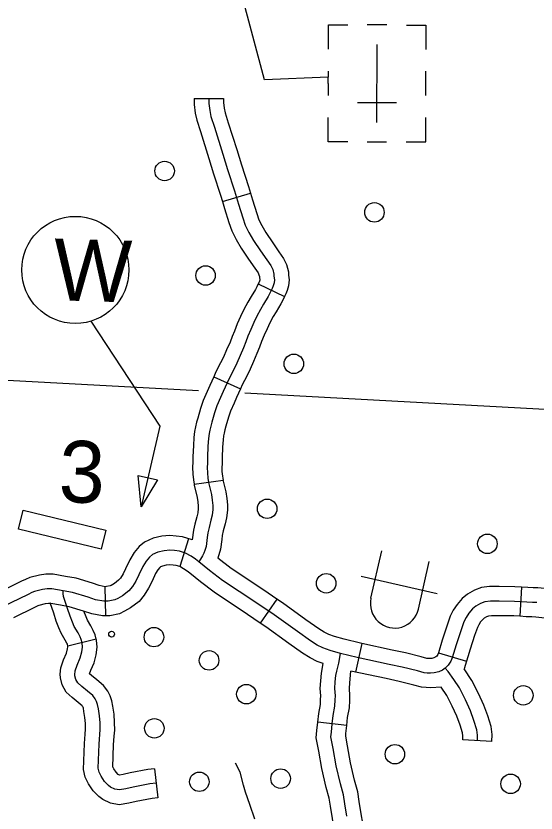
# Model space of a CAD drawing. Extents: x 653372 to 905732, y 627442 to 787275.
# Drawn here: x 716674 to 719343, y 760061 to 764152 of the extents above; entities that cross this region are included whole.
import ezdxf

# ---------------------------------------------------------------- set-up
doc = ezdxf.new("R2010")
doc.units = 0
for name, color, linetype in [('32', 7, 'Continuous'), ('35', 7, 'Continuous'), ('45', 7, 'Continuous'), ('5', 7, 'Continuous'), ('56', 7, 'Continuous'), ('57', 7, 'Continuous')]:
    doc.layers.add(name, color=color, linetype=linetype)

msp = doc.modelspace()

# ---------------------------------------------------------------- linework, layer by layer
at = {"layer": '32'}
for p, q in [((717588.6, 763729.1), (717738.6, 763728.2)), ((717733.7, 763200.2), (717877.3, 763243.3)), ((717917.3, 762776.6), (718053, 762712.7)), ((717689.2, 762299.6), (717826.2, 762238.7)), ((717588.3, 761748.6), (717736.9, 761768.8)), ((717559.5, 761468.8), (717514.7, 761325.7)), ((717130.1, 761222.7), (717133.9, 761072.8)), ((719269.2, 761220.4), (719260.3, 761070.7)), ((718012.9, 761159.2), (717928.2, 761035.4)), ((718449.2, 760931.1), (718417.3, 760784.5)), ((718842.3, 760883.6), (718986, 760840.7)), ((718372.1, 760509.9), (718223.1, 760527.5)), ((719116.7, 760428.7), (718966.9, 760436.1))]:
    msp.add_line(p, q, dxfattribs=at)
for points in [[(717588.6, 763729.1), (717588.4, 763697.9), (717594.6, 763654), (717601.8, 763617.5), (717620.8, 763558.8), (717663.8, 763421.2), (717688.7, 763342), (717724, 763232.5), (717733.7, 763200.2)], [(717663.6, 763728.6), (717663.4, 763703), (717668.6, 763666.6), (717674.6, 763636.4), (717692.3, 763581.5), (717735.3, 763443.6), (717760.1, 763364.8), (717795.6, 763254.8), (717816, 763186.6), (717838.9, 763115.2), (717851.2, 763077.6), (717869.4, 763040.2), (717893.9, 763000.4), (717929.7, 762946.3), (717962.1, 762899.7), (717981.8, 762870.7), (717991.6, 762850.2), (717997.8, 762827.4), (717998.4, 762816.1), (718000.3, 762797.2), (717998.9, 762781.9), (717994.3, 762767.1), (717989.6, 762754.1), (717977.8, 762729), (717968.9, 762711.6), (717945, 762673.1), (717928.8, 762645.8), (717910.9, 762611.9), (717894.6, 762578.7), (717878.9, 762542.9), (717865, 762507.9), (717854.5, 762479.1), (717842, 762448.2), (717824.2, 762408.7), (717808.1, 762370.2), (717791.5, 762337.4), (717767.9, 762292.1), (717737.8, 762224.3), (717724.7, 762194.6), (717704.9, 762150.8), (717692.9, 762115.5), (717679.9, 762067.8), (717673.7, 762046.9), (717668.7, 762026.7), (717665, 762008.4), (717662.4, 761982.5), (717659.6, 761943.2), (717657.7, 761887.6), (717656.8, 761857.2), (717655.1, 761834.8), (717656.5, 761807.2), (717659.7, 761779.9), (717662.8, 761757.4), (717677.8, 761695.5), (717682, 761666.6), (717684.6, 761639.4), (717684.3, 761619.4), (717681.2, 761589.1), (717674.8, 761563.4), (717665.2, 761526.2), (717659.4, 761499.2), (717655.9, 761474.5), (717650.5, 761429.7), (717644.2, 761408.3), (717638.8, 761395.3), (717632.2, 761381.8), (717621.3, 761364), (717612.8, 761351.1)], [(717738.6, 763728.2), (717738.5, 763708.1), (717742.6, 763679.1), (717747.3, 763655.3), (717763.8, 763604.2), (717806.9, 763466.1), (717831.6, 763387.5), (717867.2, 763277.1), (717877.3, 763243.3)], [(717877.3, 763243.3), (717887.7, 763208.8), (717910.2, 763138.2), (717920.9, 763105.8), (717935.3, 763076.3), (717957.1, 763040.7), (717991.8, 762988.4), (718023.9, 762942.2), (718047.1, 762908.1), (718062.2, 762876.4), (718072.2, 762839.6), (718073.2, 762821.8), (718075.6, 762797.4), (718072.8, 762767.5), (718065.5, 762743.2), (718058.9, 762725.1), (718053, 762712.8)], [(717733.7, 763200.2), (717744.4, 763164.4), (717767.5, 763092.1), (717781.5, 763049.3), (717803.6, 763004), (717830.6, 762960), (717867.7, 762904.2), (717900.3, 762857.2), (717916.6, 762833.2), (717921, 762824), (717923.4, 762815.3), (717923.7, 762810.3), (717924.9, 762797), (717924.9, 762796.4), (717923.2, 762790.9), (717920.3, 762783), (717917.3, 762776.6)], [(717917.3, 762776.6), (717910.4, 762762), (717903.5, 762748.4), (717880.8, 762712), (717863.4, 762682.4), (717844.1, 762646), (717826.6, 762610.3), (717809.7, 762571.8), (717794.9, 762534.6), (717784.5, 762506.1), (717773, 762477.7), (717755.4, 762438.6), (717739.9, 762401.6), (717724.7, 762371.6), (717700.3, 762324.7), (717689.2, 762299.6)], [(718053, 762712.8), (718045.2, 762696.1), (718034.3, 762674.7), (718009.1, 762634.2), (717994.3, 762609.2), (717977.8, 762577.9), (717962.7, 762547), (717948.1, 762513.9), (717935.1, 762481.1), (717924.5, 762452.1), (717911, 762418.8), (717893, 762378.9), (717876.2, 762338.7), (717858.2, 762303.1), (717835.5, 762259.6), (717826.2, 762238.7)], [(717689.2, 762299.6), (717669.2, 762254.6), (717656.2, 762225.1), (717635.1, 762178.4), (717621.2, 762137.5), (717607.8, 762088.4), (717601.3, 762066.6), (717595.5, 762043.1), (717590.8, 762019.6), (717587.7, 761988.9), (717584.7, 761947.2), (717582.7, 761890.1), (717581.8, 761861.1), (717580, 761835.6), (717581.7, 761801), (717585.3, 761770.5), (717588.3, 761748.6)], [(717826.2, 762238.7), (717806.3, 762193.9), (717793.2, 762164.1), (717774.8, 762123.2), (717764.7, 762093.6), (717752.1, 762047.2), (717746.1, 762027.1), (717741.9, 762010.3), (717739.3, 761997.2), (717737.1, 761976.1), (717734.6, 761939.3), (717732.6, 761885.2), (717731.7, 761853.4), (717730.3, 761833.9), (717731.3, 761813.5), (717734.1, 761789.4), (717736.9, 761768.8)], [(717736.6, 761771.3), (717751.6, 761709.7), (717756.5, 761675.5), (717759.6, 761642.4), (717759.2, 761615), (717755.3, 761576.2), (717747.5, 761545), (717738.3, 761509), (717733.3, 761485.9), (717730.2, 761464.7), (717724.2, 761414.5), (717710.7, 761368.4)], [(717588.3, 761748.7), (717589, 761743.4), (717604.1, 761681.3), (717607.5, 761657.7), (717609.5, 761636.3), (717609.3, 761623.7), (717607.1, 761602.1), (717602.1, 761581.8), (717592.2, 761543.4), (717585.6, 761512.4), (717578.4, 761462.9)], [(717578.4, 761462.9), (717529.3, 761478.3), (717496.4, 761482.6), (717463.7, 761485.3), (717423, 761481.4), (717378.4, 761472.3), (717334.3, 761451.9), (717307, 761428.3), (717281.1, 761398.7), (717258.5, 761361.3), (717237, 761315.1), (717223.8, 761287.9), (717210.4, 761266.7), (717201.4, 761255.4), (717180.3, 761239.4), (717162.8, 761229.5), (717157, 761226.8), (717139.1, 761223), (717130.1, 761222.7)], [(719346.3, 761141.5), (719324.5, 761142.2), (719296.4, 761143.7), (719231.8, 761147.5), (719153.8, 761148.6), (719109.4, 761148.7), (719080.5, 761144.5), (719057.8, 761136.4), (719033.6, 761122.8), (719016.3, 761108.3), (718998.2, 761087), (718983.8, 761064.9), (718972.5, 761042.1), (718956.7, 760995.7), (718932.9, 760924.9), (718912.7, 760857.3), (718905.3, 760840), (718892.8, 760819.8), (718877.4, 760804.6), (718863.4, 760795), (718844.3, 760786.2), (718819.8, 760780.1), (718801, 760778.8), (718784.1, 760779.3), (718768.6, 760781), (718734.5, 760790.2), (718656.9, 760809.4), (718589, 760823.9), (718425.7, 760859.5), (718340.1, 760880.2), (718286.2, 760895.5), (718249.7, 760908.5), (718220.1, 760923.1), (718186.1, 760944.1), (718118.8, 760992.4), (717998.9, 761077.9), (717905.2, 761142), (717734.9, 761254.9), (717668.3, 761306.4), (717612.8, 761351.1), (717595.6, 761364.2), (717573, 761379.2), (717544.1, 761395.1), (717513.1, 761404.8), (717488.5, 761408), (717464.2, 761410), (717434.1, 761407.1), (717402, 761400.6), (717375.4, 761388.3), (717360, 761375), (717341.9, 761354.3), (717324.8, 761326), (717304.7, 761282.9), (717289.4, 761251.4), (717271.7, 761223.2), (717254.2, 761201.2), (717221.6, 761176.6), (717197.4, 761162.9), (717181.3, 761155.3), (717148, 761148.2), (717125.4, 761147.6), (717082.6, 761155.8), (717044.2, 761168.8), (716964.9, 761193), (716916.2, 761201.9), (716859.3, 761211.8), (716834.3, 761212), (716809.8, 761207.7), (716768.9, 761198.3), (716755.6, 761192.5), (716736.5, 761183)], [(718012.9, 761159.2), (717947.1, 761204.2), (717778.6, 761316), (717710.7, 761368.4)], [(717514.7, 761325.7), (717496.9, 761331.2), (717480.5, 761333.4), (717464.7, 761334.7), (717445.1, 761332.8), (717425.6, 761328.9), (717416.4, 761324.6), (717413, 761321.6), (717402.6, 761309.8), (717391.1, 761290.7), (717372.5, 761250.6), (717355.1, 761215), (717333, 761179.8), (717306.9, 761147.1), (717262.8, 761113.8), (717232, 761096.3), (717205.5, 761083.8), (717156.8, 761073.4), (717133.9, 761072.8)], [(717928.2, 761035.4), (717863.3, 761079.8), (717691.2, 761193.9), (717621.8, 761247.5), (717566.5, 761292), (717552.1, 761303), (717534.1, 761315), (717514.6, 761325.7), (717514.7, 761325.7)], [(717131.6, 761222.8), (717101.7, 761228.5), (717067.3, 761240.2), (716982.7, 761266), (716929.4, 761275.8), (716866, 761286.8), (716828, 761287), (716794.9, 761281.3), (716745.2, 761269.8), (716723.8, 761260.4), (716703.6, 761250.4), (716596.4, 761198.8)], [(719269.2, 761220.4), (719234.6, 761222.4), (719154.3, 761223.6), (719104.1, 761223.7), (719062.5, 761217.7), (719026.6, 761204.9), (718990.7, 761184.7), (718963.3, 761161.7), (718938, 761131.9), (718918.5, 761102.2), (718903, 761071), (718885.6, 761019.7), (718861.4, 760947.5), (718842.3, 760883.6)], [(719800.6, 761122.5), (719636, 761163.2), (719490.2, 761194.1), (719446.5, 761203.6), (719413.2, 761210.5), (719387.1, 761212.7), (719351.4, 761216.4), (719327.6, 761217.1), (719300.6, 761218.5), (719269.2, 761220.4)], [(716736.5, 761183), (716561.1, 761098.6)], [(718449.2, 760931.1), (718442.5, 760932.6), (718359.2, 760952.7), (718309.1, 760967), (718279, 760977.7), (718256.6, 760988.8), (718227.7, 761006.6), (718162.4, 761053.4), (718041.8, 761139.4), (718012.9, 761159.2)], [(717133.9, 761072.8), (717119.3, 761072.4), (717063.4, 761083.1), (717021.2, 761097.4), (716947.2, 761120), (716903.1, 761128.1), (716852.6, 761136.9), (716840.6, 761136.9), (716824.6, 761134.2), (716792.6, 761126.8), (716787.4, 761124.5), (716769.5, 761115.6), (716661.4, 761063.7)], [(719260.3, 761070.7), (719229.1, 761072.5), (719153.2, 761073.6), (719114.7, 761073.6), (719098.5, 761071.3), (719089, 761067.9), (719076.5, 761060.9), (719069.3, 761054.9), (719058.4, 761042), (719049, 761027.6), (719041.9, 761013.3), (719027.7, 760971.7), (719004.4, 760902.2), (718974.3, 760801.5)], [(719764.6, 760976.9), (719602.4, 761017), (719458.7, 761047.5), (719415.5, 761056.9), (719391.6, 761061.7), (719372.9, 761063.4), (719341.3, 761066.7), (719321.4, 761067.3), (719292.2, 761068.8), (719260.3, 761070.7)], [(718251.3, 760828.3), (718220.4, 760839.3), (718183.7, 760857.5), (718144.5, 760881.7), (718075.2, 760931.4), (717955.9, 761016.4), (717928.2, 761035.4)], [(718842.3, 760883.6), (718842.1, 760882.9), (718838.6, 760874.7), (718833.8, 760866.9), (718829.6, 760862.8), (718826.2, 760860.5), (718819.3, 760857.3), (718808, 760854.5), (718799.5, 760853.9), (718789.4, 760854.2), (718782.5, 760854.9), (718753.2, 760862.8), (718673.8, 760882.5), (718604.8, 760897.2), (718449.2, 760931.1)], [(718372.2, 760045.2), (718362.2, 760107.4), (718354.8, 760153.5), (718339, 760210.3), (718317.5, 760303.4), (718302.6, 760392.6), (718290.7, 760451.8), (718292.7, 760476.7), (718297.7, 760519.2), (718302.1, 760561.6), (718311, 760609.5), (718312.6, 760641.3), (718313.2, 760662.6), (718311.2, 760700.1), (718312.9, 760733.8), (718315.8, 760767.5), (718320.2, 760789.9), (718330.8, 760830.8), (718340.1, 760880.2)], [(718223.1, 760527.5), (718223.1, 760527.5), (718227.8, 760572.4), (718236.4, 760618.3), (718237.7, 760644.3), (718238.2, 760661.7), (718236.1, 760700), (718238, 760738.9), (718241.4, 760778), (718251.3, 760828.3)], [(718372.1, 760509.9), (718372.2, 760511), (718376.4, 760550.9), (718385.7, 760600.7), (718387.5, 760638.3), (718388.3, 760663.4), (718386.3, 760700.3), (718387.7, 760728.8), (718393, 760789.8)], [(718856.7, 760707.5), (718802.5, 760703.7), (718778.9, 760704.4), (718754.7, 760707.1), (718715.7, 760717.5), (718640.1, 760736.3), (718573.2, 760750.6), (718393, 760789.8)], [(719041.8, 760432.4), (719043.2, 760461.1), (719039.6, 760488.3), (719024.5, 760536), (719006.1, 760586.3), (718980.8, 760642.3), (718949.4, 760702.9), (718920.9, 760746.2), (718891.8, 760788), (718877.4, 760804.6)], [(719116.7, 760428.7), (719118.5, 760464.2), (719113.1, 760504.6), (719095.5, 760560.2), (719075.6, 760614.7), (719048.3, 760675), (719014.3, 760740.8), (718974.3, 760801.5)], [(718966.9, 760436.1), (718968, 760458), (718966.1, 760471.9), (718953.5, 760511.8), (718936.7, 760557.9), (718913.2, 760609.6), (718884.6, 760664.9), (718856.7, 760707.5)], [(718304.4, 759992.9), (718298.1, 760033.5), (718288.1, 760095.5), (718281.4, 760137.5), (718266.3, 760191.7), (718243.9, 760288.8), (718228.9, 760379), (718215.1, 760447.2), (718218, 760484.1), (718223.1, 760527.5)], [(718453.9, 760005.2), (718453.6, 760009.6), (718446.3, 760056.9), (718436.2, 760119.3), (718428.2, 760169.5), (718411.7, 760228.8), (718391.1, 760318), (718376.4, 760406.2), (718366.3, 760456.3), (718367.3, 760469.3), (718372.1, 760509.9)]]:
    msp.add_lwpolyline(points, dxfattribs=at)
at = {"layer": '35'}
msp.add_lwpolyline([(717899.3, 760029.8), (717874.1, 760104.9), (717852.5, 760168.2), (717841.9, 760203.8), (717824.2, 760271.4), (717800.3, 760316.6)], dxfattribs=at)
at = {"layer": '45'}
for p, q in [((717086.2, 760953.6), (716940.8, 760916.8)), ((717386, 760288), (717401.9, 760138.9))]:
    msp.add_line(p, q, dxfattribs=at)
for points in [[(717394, 760213.5), (717362, 760210), (717275.3, 760193.3), (717238.8, 760185), (717204.9, 760179.8), (717181.9, 760183.6), (717159.7, 760194.5), (717149.3, 760202.3), (717129.3, 760222.9), (717111.3, 760249.7), (717100.7, 760270), (717097, 760290.8), (717100.7, 760414.4), (717106, 760489.3), (717105.8, 760523.1), (717103.1, 760559.4), (717097.4, 760595.8), (717093, 760618), (717087.9, 760633.2), (717080.8, 760647.8), (717068.8, 760663.8), (717041.4, 760687.1), (717012, 760709.8), (716992, 760729.2), (716981.3, 760747), (716976.8, 760765.3), (716976.7, 760770.6), (716978.9, 760790.9), (716988.5, 760820.6), (717004.6, 760857), (717013, 760888.3), (717016.3, 760912.6), (717013.8, 760933.9), (717009.3, 760951.6), (717003.5, 760964.9), (716992.8, 760985.2), (716973.8, 761017.7), (716964.5, 761039.8), (716951.7, 761071.5), (716939.7, 761109.9), (716925.9, 761151), (716918.4, 761171.8), (716915.8, 761187.6), (716916.2, 761201.9)], [(716940.8, 760916.8), (716938.1, 760927.1), (716935.8, 760932.4), (716927.2, 760948.8), (716906.6, 760984), (716895.1, 761011.2), (716881, 761046.2), (716868.3, 761086.9), (716850.5, 761140.1)], [(717086.2, 760953.6), (717080.5, 760976), (717071.1, 760997.4), (717058.4, 761021.6), (717041, 761051.3), (717033.8, 761068.4), (717022.2, 761097.1)], [(717178.8, 760455), (717181.1, 760486.9), (717180.8, 760526.1), (717177.7, 760568), (717171.2, 760608.9), (717165.7, 760637.4), (717157.4, 760661.7), (717145.1, 760687), (717123.7, 760715.5), (717088.7, 760745.3), (717061.2, 760766.6), (717052.6, 760775), (717052.6, 760775.1), (717058.7, 760793.8), (717075.5, 760831.9), (717086.7, 760873.6), (717091.8, 760912), (717087.7, 760947.5), (717086.2, 760953.6)], [(717029.2, 760465.7), (717031, 760491.7), (717030.8, 760520.1), (717028.6, 760550.8), (717023.5, 760582.8), (717020.4, 760598.6), (717018.4, 760604.6), (717016.5, 760608.5), (717013.8, 760612), (716994, 760628.9), (716962.9, 760653.1), (716932.8, 760682.1), (716911.1, 760718.2), (716902.1, 760755.2), (716901.6, 760773.5), (716905.1, 760806.6), (716918.4, 760847.4), (716933.7, 760882), (716939.3, 760903.1), (716940.7, 760913.2), (716939.9, 760920.3), (716940.8, 760916.8)], [(717401.9, 760138.9), (717373.1, 760135.8), (717290.7, 760119.9), (717252.8, 760111.3), (717204.4, 760103.8), (717158.7, 760111.4), (717120.2, 760130.3), (717099.5, 760145.9), (717070.7, 760175.5), (717046.8, 760211.3), (717028.9, 760245.4), (717021.8, 760285.2), (717025.7, 760418.2), (717029.2, 760465.7)], [(717386, 760288), (717350.9, 760284.3), (717259.8, 760266.7), (717224.7, 760258.7), (717205.3, 760255.7), (717205, 760255.8), (717199.1, 760258.7), (717199, 760258.7), (717187.8, 760270.3), (717175.9, 760288.1), (717172.5, 760294.7), (717172.2, 760296.4), (717175.6, 760410.6), (717178.8, 760455)]]:
    msp.add_lwpolyline(points, dxfattribs=at)
at = {"layer": '5'}
for points in [[(717610.9, 762228.2), (716376.9, 762294.7)], [(720174.1, 762090.1), (717848, 762215.4)]]:
    msp.add_lwpolyline(points, dxfattribs=at)
at = {"layer": '56'}
msp.add_lwpolyline([(716687.3, 761518.4), (716711, 761615.6), (717136, 761512), (717112.3, 761414.8)], close=True, dxfattribs=at)
for centre in [(717437.1, 763356.5), (718513.8, 763144.1), (717647.3, 762820.2), (718100.2, 762366.8), (717963.2, 761622.6), (719093.3, 761442.9), (718266.3, 761240.1), (717382.3, 760963.9), (717665.2, 760844.5), (717856.7, 760671.2), (719277.4, 760665), (717384.4, 760495.7), (718618.8, 760362.8), (717615.4, 760221.4), (718032.3, 760237.5), (719212.5, 760210.8)]:
    msp.add_circle(centre, 50, dxfattribs=at)
at = {"layer": '57'}
for p, q in [((718577.1, 764105.9), (718477.1, 764106)), ((718526.8, 763605.9), (718527.5, 764005.9)), ((718277.2, 763806.4), (718277.3, 763869.7)), ((718777.1, 763743.9), (718777.3, 763868.9)), ((718277.2, 763806.4), (718277.1, 763744.7)), ((718527.2, 763805.9), (718527.2, 763805.9)), ((718527.2, 763805.9), (718527.2, 763805.9)), ((718627, 763705.8), (718426.1, 763706.1)), ((718476.1, 763506), (718576.1, 763505.9)), ((717317.6, 761632.7), (717302.1, 761793.2)), ((717302.1, 761793.2), (717401.5, 761770.4)), ((717401.5, 761770.4), (717317.6, 761632.7)), ((718496.1, 761163), (718551.7, 761406.7)), ((718739.9, 761107.4), (718795.4, 761351.2)), ((718445.2, 761277.2), (718835.2, 761188.3))]:
    msp.add_line(p, q, dxfattribs=at)
for points in [[(718277.2, 763838.1), (717949.3, 763823.9), (717770.1, 764497.8)], [(718277.5, 763981.4), (718277.7, 764106.4), (718377.7, 764106.2)], [(718677.7, 764105.7), (718777.7, 764105.5), (718777.5, 763980.5)], [(718376.7, 763506.2), (718276.7, 763506.4), (718276.9, 763631.4)], [(718676.7, 763505.7), (718776.7, 763505.5), (718776.9, 763630.5)], [(717059.1, 762585.4), (717412.5, 762046), (717317.6, 761632.7)]]:
    msp.add_lwpolyline(points, dxfattribs=at)
for centre, radius in [((716979, 762848.5), 275), ((717165.1, 760979.3), 15)]:
    msp.add_circle(centre, radius, dxfattribs=at)
msp.add_arc((718618, 761135.2), 125, 167.1634, 347.1634, dxfattribs=at)

# ---------------------------------------------------------------- texts
at = {"layer": '56'}
msp.add_text('3', height=316.8, rotation=358.28, dxfattribs=at).set_placement((716890.9, 761657.6))
at = {"layer": '57'}
msp.add_text('W', height=316.8, rotation=358.28, dxfattribs=at).set_placement((716863.3, 762693.5))

doc.saveas('drawing.dxf')
